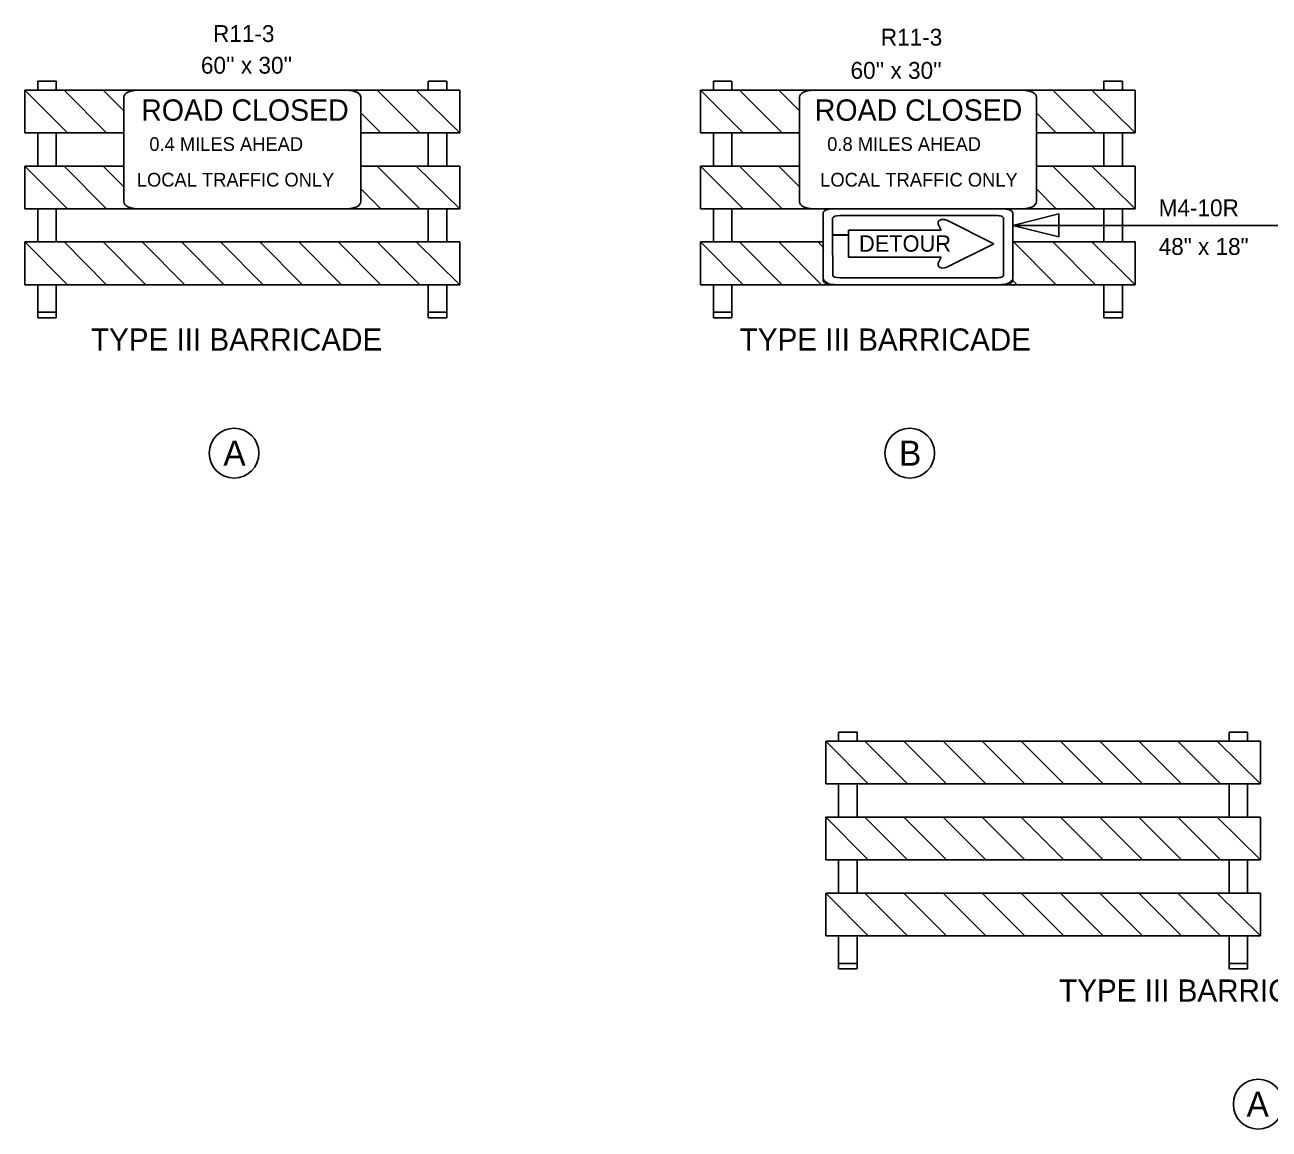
# Model space of a CAD drawing. Extents: x 2157572 to 5059327, y 715220 to 1674494.
# Drawn here: x 2159020 to 2161225, y 719509 to 721465 of the extents above; entities that cross this region are included whole.
import ezdxf

# ---------------------------------------------------------------- set-up
doc = ezdxf.new("R2010")
doc.units = 0
for name, color, linetype in [('Exist Cultural Church Label', 7, 'Continuous'), ('Exist Road Secondary Structure Culvert Number Label', 7, 'Continuous'), ('Level 54', 7, 'Continuous'), ('Map Preparation Border Control Points', 7, 'Continuous'), ('Map Preparation County Base Legend Highway Garage or Maintenance Office', 7, 'Continuous'), ('Map Preparation County Base Legend Lighthouse', 7, 'Continuous'), ('Map Preparation County Inset Control Points', 7, 'Continuous')]:
    doc.layers.add(name, color=color, linetype=linetype)

msp = doc.modelspace()

# ---------------------------------------------------------------- linework, layer by layer
at = {"layer": 'Exist Cultural Church Label'}
for centre in [(2159390.7, 720706.7), (2160588.3, 720706.7), (2161206, 719553.4)]:
    msp.add_circle(centre, 44.1, dxfattribs=at)
at = {"layer": 'Exist Road Secondary Structure Culvert Number Label'}
for p, q in [((2160462.2, 720212.7), (2160494.9, 720212.7)), ((2160462.2, 720212.7), (2160462.2, 720196.3)), ((2160494.9, 720212.7), (2160494.9, 720196.3)), ((2161154.3, 720212.7), (2161187, 720212.7)), ((2161154.3, 720212.7), (2161154.3, 720196.3)), ((2161187, 720212.7), (2161187, 720196.3)), ((2161209.9, 720196.3), (2160439.3, 720196.3)), ((2160439.3, 720196.3), (2160439.3, 720120.8)), ((2160508.7, 720196.3), (2160439.3, 720196.3)), ((2160439.3, 720196.3), (2160514.9, 720120.8)), ((2160584.2, 720120.8), (2160508.7, 720196.3)), ((2160647.3, 720196.3), (2160578, 720196.3)), ((2160578, 720196.3), (2160653.6, 720120.8)), ((2160722.9, 720120.8), (2160647.3, 720196.3)), ((2160786, 720196.3), (2160716.7, 720196.3)), ((2160716.7, 720196.3), (2160792.2, 720120.8)), ((2160861.6, 720120.8), (2160786, 720196.3)), ((2160925, 720196.3), (2160855.7, 720196.3)), ((2160855.7, 720196.3), (2160931.3, 720120.8)), ((2161000.6, 720120.8), (2160925, 720196.3)), ((2161063.7, 720196.3), (2160994.4, 720196.3)), ((2160994.4, 720196.3), (2161069.9, 720120.8)), ((2161139.3, 720120.8), (2161063.7, 720196.3)), ((2161209.9, 720196.3), (2161133.1, 720196.3)), ((2161133.1, 720196.3), (2161209.9, 720120.8)), ((2161209.9, 720120.8), (2161209.9, 720196.3)), ((2161209.9, 720120.8), (2161209.9, 720196.3)), ((2160439.3, 720120.8), (2161209.9, 720120.8)), ((2160462.2, 720120.8), (2160462.2, 720061.9)), ((2160494.9, 720120.8), (2160494.9, 720061.9)), ((2160514.9, 720120.8), (2160584.2, 720120.8)), ((2160653.6, 720120.8), (2160722.9, 720120.8)), ((2160792.2, 720120.8), (2160861.6, 720120.8)), ((2160931.3, 720120.8), (2161000.6, 720120.8)), ((2161069.9, 720120.8), (2161139.3, 720120.8)), ((2161154.3, 720120.8), (2161154.3, 720061.9)), ((2161187, 720120.8), (2161187, 720061.9)), ((2161209.9, 720061.9), (2160439.3, 720061.9)), ((2160439.3, 720061.9), (2160439.3, 719986.3)), ((2160508.7, 720061.9), (2160439.3, 720061.9)), ((2160439.3, 720061.9), (2160514.9, 719986.3)), ((2160584.2, 719986.3), (2160508.7, 720061.9)), ((2160647.3, 720061.9), (2160578, 720061.9)), ((2160578, 720061.9), (2160653.6, 719986.3)), ((2160722.9, 719986.3), (2160647.3, 720061.9)), ((2160786, 720061.9), (2160716.7, 720061.9)), ((2160716.7, 720061.9), (2160792.2, 719986.3)), ((2160861.6, 719986.3), (2160786, 720061.9)), ((2160925, 720061.9), (2160855.7, 720061.9)), ((2160855.7, 720061.9), (2160931.3, 719986.3)), ((2161000.6, 719986.3), (2160925, 720061.9)), ((2161063.7, 720061.9), (2160994.4, 720061.9)), ((2160994.4, 720061.9), (2161069.9, 719986.3)), ((2161139.3, 719986.3), (2161063.7, 720061.9)), ((2161209.9, 720061.9), (2161133.1, 720061.9)), ((2161133.1, 720061.9), (2161209.9, 719986.3)), ((2161209.9, 719986.3), (2161209.9, 720061.9)), ((2161209.9, 719986.3), (2161209.9, 720061.9)), ((2160439.3, 719986.3), (2161209.9, 719986.3)), ((2160462.2, 719986.3), (2160462.2, 719927.5)), ((2160494.9, 719986.3), (2160494.9, 719927.5)), ((2160514.9, 719986.3), (2160584.2, 719986.3)), ((2160653.6, 719986.3), (2160722.9, 719986.3)), ((2160792.2, 719986.3), (2160861.6, 719986.3)), ((2160931.3, 719986.3), (2161000.6, 719986.3)), ((2161069.9, 719986.3), (2161139.3, 719986.3)), ((2161154.3, 719986.3), (2161154.3, 719927.5)), ((2161187, 719986.3), (2161187, 719927.5)), ((2160508.7, 719927.5), (2160439.3, 719927.5)), ((2160439.3, 719927.5), (2160514.9, 719851.9)), ((2161209.9, 719927.5), (2160439.3, 719927.5)), ((2160439.3, 719927.5), (2160439.3, 719851.9)), ((2160584.2, 719851.9), (2160508.7, 719927.5)), ((2160647.3, 719927.5), (2160578, 719927.5)), ((2160578, 719927.5), (2160653.6, 719851.9)), ((2160722.9, 719851.9), (2160647.3, 719927.5)), ((2160786, 719927.5), (2160716.7, 719927.5)), ((2160716.7, 719927.5), (2160792.2, 719851.9)), ((2160861.6, 719851.9), (2160786, 719927.5)), ((2160925, 719927.5), (2160855.7, 719927.5)), ((2160855.7, 719927.5), (2160931.3, 719851.9)), ((2161000.6, 719851.9), (2160925, 719927.5)), ((2161063.7, 719927.5), (2160994.4, 719927.5)), ((2160994.4, 719927.5), (2161069.9, 719851.9)), ((2161139.3, 719851.9), (2161063.7, 719927.5)), ((2161209.9, 719927.5), (2161133.1, 719927.5)), ((2161133.1, 719927.5), (2161209.9, 719851.9)), ((2161209.9, 719851.9), (2161209.9, 719927.5)), ((2161209.9, 719851.9), (2161209.9, 719927.5)), ((2160439.3, 719851.9), (2161209.9, 719851.9)), ((2160462.2, 719851.9), (2160462.2, 719793)), ((2160494.9, 719851.9), (2160494.9, 719793)), ((2160514.9, 719851.9), (2160584.2, 719851.9)), ((2160653.6, 719851.9), (2160722.9, 719851.9)), ((2160792.2, 719851.9), (2160861.6, 719851.9)), ((2160931.3, 719851.9), (2161000.6, 719851.9)), ((2161069.9, 719851.9), (2161139.3, 719851.9)), ((2161154.3, 719851.9), (2161154.3, 719793)), ((2161187, 719851.9), (2161187, 719793)), ((2160462.2, 719802.8), (2160494.9, 719802.8)), ((2161154.3, 719802.8), (2161187, 719802.8)), ((2160462.2, 719793), (2160494.9, 719793)), ((2161154.3, 719793), (2161187, 719793))]:
    msp.add_line(p, q, dxfattribs=at)
at = {"layer": 'Map Preparation Border Control Points'}
for p, q in [((2160988.1, 721349.7), (2160217.5, 721349.7)), ((2160217.5, 721349.7), (2160217.5, 721274.1)), ((2160286.8, 721349.7), (2160217.5, 721349.7)), ((2160217.5, 721349.7), (2160293, 721274.1)), ((2160240.4, 721366), (2160273.1, 721366)), ((2160240.4, 721366), (2160240.4, 721349.7)), ((2160273.1, 721366), (2160273.1, 721349.7)), ((2160362.4, 721274.1), (2160286.8, 721349.7)), ((2160392.8, 721313), (2160356.2, 721349.7)), ((2160356.2, 721349.7), (2160417.1, 721349.7)), ((2160841.9, 721349.7), (2160788.3, 721349.7)), ((2160917.4, 721274.1), (2160841.9, 721349.7)), ((2160988.1, 721349.7), (2160911.2, 721349.7)), ((2160911.2, 721349.7), (2160988.1, 721274.1)), ((2160932.5, 721366), (2160965.2, 721366)), ((2160932.5, 721366), (2160932.5, 721349.7)), ((2160965.2, 721366), (2160965.2, 721349.7)), ((2160988.1, 721274.1), (2160988.1, 721349.7)), ((2160988.1, 721274.1), (2160988.1, 721349.7)), ((2160392.8, 721337.4), (2160392.8, 721313)), ((2160392.8, 721337.4), (2160392.8, 721337.4)), ((2160812.8, 721337.4), (2160812.8, 721309.4)), ((2160812.8, 721309.4), (2160848.1, 721274.1)), ((2160217.5, 721274.1), (2160392.8, 721274.1)), ((2160240.4, 721274.1), (2160240.4, 721215.2)), ((2160273.1, 721274.1), (2160273.1, 721215.2)), ((2160293, 721274.1), (2160362.4, 721274.1)), ((2160812.8, 721274.1), (2160988.1, 721274.1)), ((2160848.1, 721274.1), (2160917.4, 721274.1)), ((2160932.5, 721274.1), (2160932.5, 721215.2)), ((2160965.2, 721274.1), (2160965.2, 721215.2)), ((2160217.5, 721215.2), (2160217.5, 721139.7)), ((2160286.8, 721215.2), (2160217.5, 721215.2)), ((2160217.5, 721215.2), (2160293, 721139.7)), ((2160392.8, 721215.2), (2160217.5, 721215.2)), ((2160362.4, 721139.7), (2160286.8, 721215.2)), ((2160392.8, 721215.2), (2160356.2, 721215.2)), ((2160356.2, 721215.2), (2160392.8, 721178.6)), ((2160392.8, 721178.6), (2160392.8, 721215.2)), ((2160988.1, 721215.2), (2160812.8, 721215.2)), ((2160841.9, 721215.2), (2160812.8, 721215.2)), ((2160917.4, 721139.7), (2160841.9, 721215.2)), ((2160988.1, 721215.2), (2160911.2, 721215.2)), ((2160911.2, 721215.2), (2160988.1, 721139.7)), ((2160988.1, 721139.7), (2160988.1, 721215.2)), ((2160988.1, 721139.7), (2160988.1, 721215.2)), ((2160217.5, 721139.7), (2160988.1, 721139.7)), ((2160240.4, 721139.7), (2160240.4, 721080.8)), ((2160273.1, 721139.7), (2160273.1, 721080.8)), ((2160293, 721139.7), (2160362.4, 721139.7)), ((2160741.9, 721127.6), (2160464.4, 721127.9)), ((2160848.1, 721139.7), (2160917.4, 721139.7)), ((2160932.5, 721139.7), (2160932.5, 721080.8)), ((2160965.2, 721139.7), (2160965.2, 721080.8)), ((2160451.6, 721123.4), (2160451.6, 721093.6)), ((2160643.8, 721101.6), (2160638.9, 721112.5)), ((2160652.7, 721119.9), (2160737.6, 721077.4)), ((2160754.4, 721021.6), (2160754.4, 721123.4)), ((2160770.8, 721110.3), (2161364.1, 721110.3)), ((2160286.8, 721080.8), (2160217.5, 721080.8)), ((2160217.5, 721080.8), (2160293, 721005.2)), ((2160217.5, 721080.8), (2160217.5, 721005.2)), ((2160434.8, 721080.8), (2160217.5, 721080.8)), ((2160362.4, 721005.2), (2160286.8, 721080.8)), ((2160356.2, 721080.8), (2160431.7, 721005.2)), ((2160425.5, 721080.8), (2160356.2, 721080.8)), ((2160434.8, 721071.5), (2160425.5, 721080.8)), ((2160451.6, 721093.6), (2160479.5, 721093.6)), ((2160479.5, 721092.7), (2160451.6, 721092.7)), ((2160451.6, 721092.7), (2160452, 721021.6)), ((2160479.5, 721093.6), (2160479.5, 721101.6)), ((2160479.5, 721101.6), (2160643.8, 721101.6)), ((2160479.5, 721053.7), (2160479.5, 721092.7)), ((2160988.1, 721080.8), (2160770.8, 721080.8)), ((2160841.9, 721080.8), (2160772.5, 721080.8)), ((2160772.5, 721080.8), (2160848.1, 721005.2)), ((2160917.4, 721005.2), (2160841.9, 721080.8)), ((2160988.1, 721080.8), (2160911.2, 721080.8)), ((2160911.2, 721080.8), (2160988.1, 721005.2)), ((2160988.1, 721005.2), (2160988.1, 721080.8)), ((2160988.1, 721005.2), (2160988.1, 721080.8)), ((2160434.8, 721017.5), (2160434.8, 721071.5)), ((2160737.6, 721077.4), (2160652.7, 721035.8)), ((2160643.8, 721053.7), (2160479.5, 721053.7)), ((2160638.9, 721043.1), (2160643.8, 721053.7)), ((2160464.7, 721017.3), (2160741.9, 721017.3)), ((2160778.7, 721005.2), (2160770, 721014)), ((2160217.5, 721005.2), (2160988.1, 721005.2)), ((2160240.4, 721005.2), (2160240.4, 720946.4)), ((2160273.1, 721005.2), (2160273.1, 720946.4)), ((2160293, 721005.2), (2160362.4, 721005.2)), ((2160431.7, 721005.2), (2160454.3, 721005.2)), ((2160751.2, 721005.2), (2160454.4, 721005.2)), ((2160751.2, 721005.2), (2160778.7, 721005.2)), ((2160848.1, 721005.2), (2160917.4, 721005.2)), ((2160932.5, 721005.2), (2160932.5, 720946.4)), ((2160965.2, 721005.2), (2160965.2, 720946.4)), ((2160240.4, 720956.2), (2160273.1, 720956.2)), ((2160932.5, 720956.2), (2160965.2, 720956.2)), ((2160240.4, 720946.4), (2160273.1, 720946.4)), ((2160932.5, 720946.4), (2160965.2, 720946.4))]:
    msp.add_line(p, q, dxfattribs=at)
for points in [[(2159590.7, 721349.7), (2159219.8, 721349.7)], [(2160788.3, 721349.7), (2160417.3, 721349.7)], [(2159195.3, 721337.4), (2159195.3, 721151.9)], [(2159615.2, 721151.9), (2159615.2, 721337.4)], [(2160392.8, 721337.4), (2160392.8, 721151.9)], [(2160812.8, 721151.9), (2160812.8, 721337.4)], [(2160812.8, 721215.2), (2160812.8, 721175), (2160848.1, 721139.7)], [(2159219.8, 721139.7), (2159590.7, 721139.7)], [(2159256.9, 721139.7), (2159553.6, 721139.7)], [(2160417.3, 721139.7), (2160788.3, 721139.7)], [(2160434.8, 721012.6), (2160434.8, 721132.3)], [(2160454.4, 721139.7), (2160751.2, 721139.7)], [(2160770.8, 721132.3), (2160770.8, 721012.6)]]:
    msp.add_lwpolyline(points, dxfattribs=at)
msp.add_lwpolyline([(2160852.5, 721089.8), (2160770.8, 721110.3), (2160852.5, 721130.7)], close=True, dxfattribs=at)
msp.add_lwpolyline([(2160852.5, 721089.8), (2160770.8, 721110.3), (2160852.5, 721130.7)], close=True, dxfattribs=at)
for centre, major_axis, ratio, start_param, end_param in [((2159219.8, 721337.4), (-24.5, 0), 0.5, 4.712304, 6.283185), ((2159590.7, 721337.4), (24.5, 0), 0.5, 0, 1.571024), ((2160417.3, 721337.4), (-24.5, 0), 0.5, 4.712304, 6.283185), ((2160417.3, 721337.4), (-24.5, 0), 0.5, 4.712389, 6.283185), ((2160788.3, 721337.4), (24.5, 0), 0.5, 0, 1.571024), ((2160788.3, 721337.4), (24.5, 0), 0.5, 0, 1.571024), ((2159219.8, 721151.9), (24.5, 0), 0.5, 3.141593, 4.712389), ((2159590.7, 721151.9), (24.5, 0), 0.5, 4.712389, 6.283185), ((2160417.3, 721151.9), (24.5, 0), 0.5, 3.141593, 4.712389), ((2160788.3, 721151.9), (24.5, 0), 0.5, 4.712389, 6.283185), ((2160454.4, 721132.3), (-19.6, 0), 0.375009, 4.712162, 6.283185), ((2160464.5, 721123.4), (-12.6, 0), 0.337508, 4.712581, 6.283188), ((2160741.8, 721123.4), (12.6, 0), 0.337508, 6.283178, 7.854173), ((2160751.2, 721132.3), (19.6, 0), 0.375009, 0, 1.570796), ((2160647.4, 721114.3), (9, 0), 0.720018, 0.96961, 3.452569), ((2160647.4, 721041.1), (9, 0), 0.720018, 2.830617, 5.313577), ((2160454.4, 721017.5), (19.6, 0), 0.625, 3.141593, 4.712389), ((2160464.7, 721021.6), (-12.6, 0), 0.337508, 0.000003, 1.57061), ((2160741.9, 721021.6), (12.6, 0), 0.337508, 4.712203, 6.283178), ((2160751.2, 721017.5), (19.6, 0), 0.625, 4.712497, 5.996053), ((2160454.4, 721012.6), (-19.6, 0), 0.375009, 0, 1.570796), ((2160751.2, 721012.6), (-19.6, 0), 0.375009, 1.570796, 3.141593)]:
    msp.add_ellipse(centre, major_axis=major_axis, ratio=ratio, start_param=start_param, end_param=end_param, dxfattribs=at)
at = {"layer": 'Map Preparation County Base Legend Highway Garage or Maintenance Office'}
for centre in [(2159390.7, 720706.7), (2160588.3, 720706.7), (2161206, 719553.4)]:
    msp.add_circle(centre, 44.1, dxfattribs=at)
at = {"layer": 'Map Preparation County Base Legend Lighthouse'}
for p, q in [((2159019.9, 721349.7), (2159790.6, 721349.7)), ((2159019.9, 721274.1), (2159019.9, 721349.7)), ((2159089.3, 721349.7), (2159019.9, 721349.7)), ((2159019.9, 721349.7), (2159095.5, 721274.1)), ((2159075.5, 721366), (2159042.8, 721366)), ((2159042.8, 721366), (2159042.8, 721349.7)), ((2159075.5, 721366), (2159075.5, 721349.7)), ((2159164.8, 721274.1), (2159089.3, 721349.7)), ((2159228, 721349.7), (2159158.6, 721349.7)), ((2159158.6, 721349.7), (2159195.3, 721313)), ((2159219.6, 721349.7), (2159228, 721349.7)), ((2159644.3, 721349.7), (2159575, 721349.7)), ((2159719.9, 721274.1), (2159644.3, 721349.7)), ((2159790.6, 721349.7), (2159713.7, 721349.7)), ((2159713.7, 721349.7), (2159790.6, 721274.1)), ((2159767.7, 721366), (2159734.9, 721366)), ((2159734.9, 721366), (2159734.9, 721349.7)), ((2159767.7, 721366), (2159767.7, 721349.7)), ((2159790.6, 721349.7), (2159790.6, 721274.1)), ((2159790.6, 721274.1), (2159790.6, 721349.7)), ((2159195.3, 721274.1), (2159019.9, 721274.1)), ((2159042.8, 721274.1), (2159042.8, 721215.2)), ((2159075.5, 721274.1), (2159075.5, 721215.2)), ((2159095.5, 721274.1), (2159164.8, 721274.1)), ((2159790.6, 721274.1), (2159615.2, 721274.1)), ((2159650.6, 721274.1), (2159719.9, 721274.1)), ((2159734.9, 721274.1), (2159734.9, 721215.2)), ((2159767.7, 721274.1), (2159767.7, 721215.2)), ((2159019.9, 721139.7), (2159019.9, 721215.2)), ((2159089.3, 721215.2), (2159019.9, 721215.2)), ((2159019.9, 721215.2), (2159095.5, 721139.7)), ((2159019.9, 721215.2), (2159195.3, 721215.2)), ((2159164.8, 721139.7), (2159089.3, 721215.2)), ((2159195.3, 721215.2), (2159158.6, 721215.2)), ((2159158.6, 721215.2), (2159195.3, 721178.6)), ((2159195.3, 721197.4), (2159195.3, 721215.2)), ((2159615.2, 721215.2), (2159790.6, 721215.2)), ((2159719.9, 721139.7), (2159644.3, 721215.2)), ((2159790.6, 721215.2), (2159713.7, 721215.2)), ((2159713.7, 721215.2), (2159790.6, 721139.7)), ((2159790.6, 721215.2), (2159790.6, 721139.7)), ((2159790.6, 721139.7), (2159790.6, 721215.2)), ((2159195.3, 721178.6), (2159195.3, 721197.4)), ((2159615.2, 721175), (2159650.6, 721139.7)), ((2159790.6, 721139.7), (2159019.9, 721139.7)), ((2159042.8, 721139.7), (2159042.8, 721080.8)), ((2159075.5, 721139.7), (2159075.5, 721080.8)), ((2159095.5, 721139.7), (2159164.8, 721139.7)), ((2159650.6, 721139.7), (2159719.9, 721139.7)), ((2159734.9, 721139.7), (2159734.9, 721080.8)), ((2159767.7, 721139.7), (2159767.7, 721080.8)), ((2159089.3, 721080.8), (2159019.9, 721080.8)), ((2159019.9, 721080.8), (2159095.5, 721005.2)), ((2159019.9, 721080.8), (2159790.6, 721080.8)), ((2159019.9, 721005.2), (2159019.9, 721080.8)), ((2159164.8, 721005.2), (2159089.3, 721080.8)), ((2159228, 721080.8), (2159158.6, 721080.8)), ((2159158.6, 721080.8), (2159234.2, 721005.2)), ((2159303.5, 721005.2), (2159228, 721080.8)), ((2159366.6, 721080.8), (2159297.3, 721080.8)), ((2159297.3, 721080.8), (2159372.9, 721005.2)), ((2159442.2, 721005.2), (2159366.6, 721080.8)), ((2159505.7, 721080.8), (2159436.3, 721080.8)), ((2159436.3, 721080.8), (2159511.9, 721005.2)), ((2159581.2, 721005.2), (2159505.7, 721080.8)), ((2159644.3, 721080.8), (2159575, 721080.8)), ((2159575, 721080.8), (2159650.6, 721005.2)), ((2159719.9, 721005.2), (2159644.3, 721080.8)), ((2159790.6, 721080.8), (2159713.7, 721080.8)), ((2159713.7, 721080.8), (2159790.6, 721005.2)), ((2159790.6, 721005.2), (2159790.6, 721080.8)), ((2159790.6, 721080.8), (2159790.6, 721005.2)), ((2159790.6, 721005.2), (2159019.9, 721005.2)), ((2159042.8, 721005.2), (2159042.8, 720946.4)), ((2159075.5, 721005.2), (2159075.5, 720946.4)), ((2159095.5, 721005.2), (2159164.8, 721005.2)), ((2159234.2, 721005.2), (2159303.5, 721005.2)), ((2159372.9, 721005.2), (2159442.2, 721005.2)), ((2159511.9, 721005.2), (2159581.2, 721005.2)), ((2159650.6, 721005.2), (2159719.9, 721005.2)), ((2159734.9, 721005.2), (2159734.9, 720946.4)), ((2159767.7, 721005.2), (2159767.7, 720946.4)), ((2159075.5, 720956.2), (2159042.8, 720956.2)), ((2159767.7, 720956.2), (2159734.9, 720956.2)), ((2159075.5, 720946.4), (2159042.8, 720946.4)), ((2159767.7, 720946.4), (2159734.9, 720946.4))]:
    msp.add_line(p, q, dxfattribs=at)
for points in [[(2159195.3, 721313), (2159195.3, 721337.6), (2159196.2, 721340.9), (2159198.8, 721343.8), (2159202.4, 721346.1), (2159208.5, 721348.3), (2159214.3, 721349.4), (2159219.6, 721349.7)], [(2159575, 721349.7), (2159594, 721349.5), (2159598.7, 721349), (2159602.9, 721348), (2159605.9, 721347), (2159608.8, 721345.7), (2159611.2, 721344.1), (2159613.1, 721342.4), (2159614.2, 721340.9), (2159615.2, 721337.4), (2159615.2, 721309.4), (2159650.6, 721274.1)], [(2159644.3, 721215.2), (2159615.2, 721215.2), (2159615.2, 721175)]]:
    msp.add_lwpolyline(points, dxfattribs=at)
at = {"layer": 'Map Preparation County Inset Control Points'}
msp.add_lwpolyline([(2159256.9, 721349.7), (2159553.6, 721349.7)], dxfattribs=at)

# ---------------------------------------------------------------- texts
at = {"layer": 'Exist Cultural Church Label'}
for s, p in [('A', (2159371.7, 720684.6)), ('B', (2160569.3, 720684.6)), ('A', (2161185.3, 719531.2))]:
    msp.add_text(s, height=44.3, dxfattribs=at).set_placement(p)
at = {"layer": 'Exist Road Secondary Structure Culvert Number Label'}
for s, height, p in [('R11-3', 29.88, (2159353.5, 721435.1)), ("60'' x 30''", 29.88, (2159332, 721379)), ('TYPE III BARRICADE(S)', 39.25, (2160853.1, 719735.1))]:
    msp.add_text(s, height=height, dxfattribs=at).set_placement(p)
at = {"layer": 'Level 54'}
for s, height, p in [('ROAD CLOSED', 37.785, (2159226.1, 721295.6)), ('0.4 MILES AHEAD', 24.287, (2159240.5, 721242.1)), ('LOCAL TRAFFIC ONLY', 24.287, (2159218.3, 721179))]:
    msp.add_text(s, height=height, dxfattribs=at).set_placement(p)
at = {"layer": 'Map Preparation Border Control Points'}
for s, height, p in [('R11-3', 29.88, (2160537.1, 721428.7)), ("60'' x 30''", 29.88, (2160483.4, 721369.9)), ('ROAD CLOSED', 37.785, (2160420, 721295.6)), ('0.8 MILES AHEAD', 24.287, (2160442, 721242.1)), ('LOCAL TRAFFIC ONLY', 24.287, (2160429.6, 721179)), ('M4-10R', 29.88, (2161029.5, 721126.4)), ('DETOUR', 28.88, (2160498.4, 721063.7)), ('48" x 18"', 29.88, (2161029.5, 721057.9)), ('TYPE III BARRICADE', 39.25, (2160286.9, 720888.4))]:
    msp.add_text(s, height=height, dxfattribs=at).set_placement(p)
at = {"layer": 'Map Preparation County Base Legend Lighthouse'}
msp.add_text('TYPE III BARRICADE', height=39.25, dxfattribs=at).set_placement((2159137, 720888.4))

doc.saveas('drawing.dxf')
